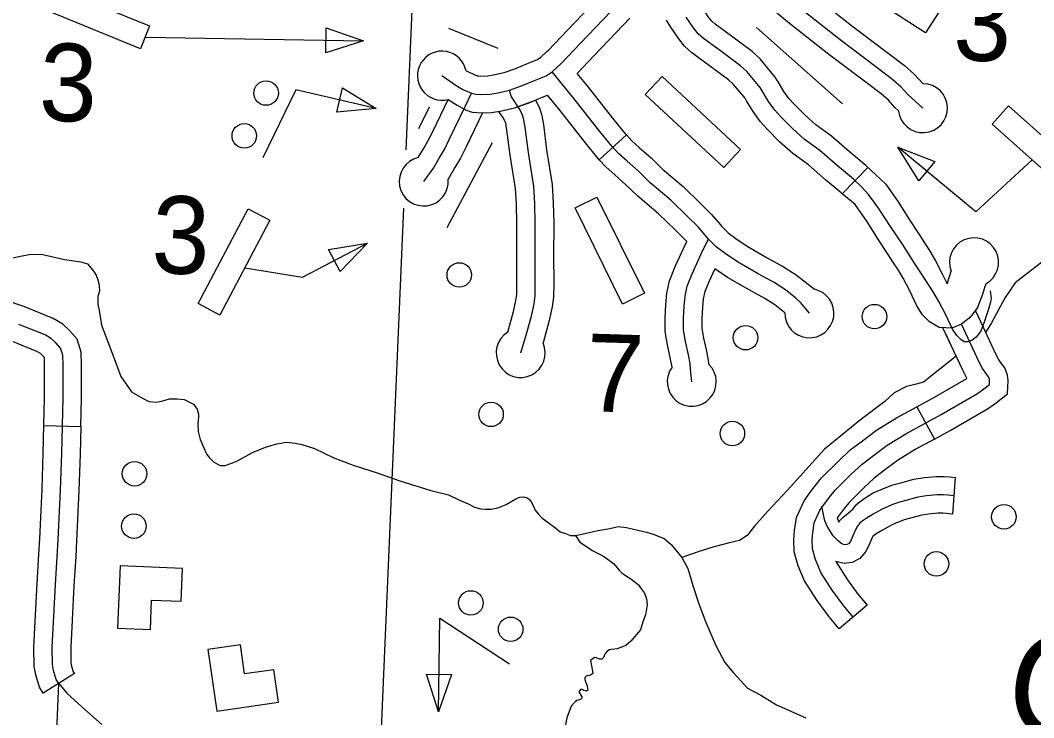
# Model space of a CAD drawing. Extents: x 653372 to 905732, y 627442 to 787275.
# Drawn here: x 662227 to 666359, y 765522 to 768368 of the extents above; entities that cross this region are included whole.
import ezdxf

# ---------------------------------------------------------------- set-up
doc = ezdxf.new("R2010")
doc.units = 0
for name, color, linetype in [('31', 7, 'Continuous'), ('33', 7, 'Continuous'), ('35', 7, 'Continuous'), ('5', 7, 'Continuous'), ('56', 7, 'Continuous'), ('58', 7, 'Continuous'), ('6', 7, 'Continuous')]:
    doc.layers.add(name, color=color, linetype=linetype)

msp = doc.modelspace()

# ---------------------------------------------------------------- linework, layer by layer
at = {"layer": '31'}
for p, q in [((664587.8, 767799), (664698.6, 767900.2)), ((664698.6, 767900.2), (664698.6, 767900.2)), ((665577.6, 767660.4), (665682.3, 767767.7)), ((665883, 766791.2), (665954.7, 766659.4)), ((662323.4, 766714.6), (662473.4, 766711)), ((666039.2, 766503), (666027.4, 766353.5)), ((665680.6, 765981.7), (665565.9, 765884.9)), ((662447.5, 765702.2), (662320.1, 765623.1)), ((662320.1, 765623.1), (662320.1, 765623.1))]:
    msp.add_line(p, q, dxfattribs=at)
for points in [[(665907.2, 768009.4), (665846.2, 768065.8), (665819.1, 768095.2), (665785.3, 768125.6), (665720.6, 768173.9), (665570, 768287.8), (665403.6, 768418.9), (665329.5, 768480.5), (665294.2, 768507.4), (665276.9, 768519.5), (665256.6, 768527), (665232.9, 768532.4), (665195.6, 768536.3), (665156, 768535.4), (665115.6, 768529.1), (664959, 768466.4), (664923.1, 768449), (664901.8, 768433.2)], [(663946.3, 768142.1), (664003.8, 768102.2), (664031.9, 768085.7), (664066.9, 768070.3), (664084.9, 768066.4), (664102.6, 768065.2), (664140.8, 768066.7), (664175.8, 768072.5), (664221, 768082.7), (664270.6, 768100.3), (664323.1, 768122), (664370.7, 768141.7), (664395.5, 768157.4), (664432.9, 768192.3), (664511, 768274.5), (664603.1, 768370.6), (664670.7, 768440.8), (664689.4, 768464.1)], [(664374.1, 768240), (664380.1, 768245.6), (664456.7, 768326.3), (664549.1, 768422.5), (664594.8, 768470.1)], [(665453, 768284.6), (665356.4, 768360.6), (665282.8, 768421.8), (665250, 768446.8), (665241.9, 768452.5), (665235.2, 768454.9), (665220.6, 768458.3), (665192.5, 768461.2), (665162.6, 768460.6), (665135.6, 768456.4), (665069, 768429.6)], [(664497.5, 768151.4), (664565.2, 768222.7), (664657.2, 768318.6), (664712.8, 768376.4)], [(666181.7, 767264.6), (666183.7, 767242), (666185.6, 767234.5), (666182.3, 767218.2), (666173.2, 767185.8), (666157.5, 767135.8), (666143.5, 767100.1), (666132.8, 767085.4), (666124.3, 767074.8), (666107.6, 767062.3), (666092.4, 767056), (666076.1, 767056.5), (666062, 767065.1), (666045.5, 767081.9), (666028.6, 767108.3), (666001, 767165.7), (665972.7, 767221.1), (665948.6, 767260.7), (665907, 767325), (665870.5, 767381.3), (665824.3, 767454.2), (665774.7, 767526.6), (665729.5, 767597.2), (665708.5, 767625.8), (665684.9, 767657.2), (665656.6, 767688.1), (665624.1, 767719.7), (665559, 767774.2), (665487.2, 767836.3), (665423.4, 767882.9), (665375, 767925.9), (665328, 767974.2), (665302.9, 768000.9), (665277.4, 768036.4), (665243.7, 768093.3), (665216.7, 768126.2), (665189.1, 768158.4), (665163.2, 768182.3), (665081.9, 768242.7), (665012.8, 768293.5), (664990.9, 768313.3), (664972.5, 768337), (664942.5, 768380.9)], [(665317.2, 768116.4), (665305.3, 768136.5), (665274.2, 768174.4), (665243.2, 768210.5), (665211.2, 768240.1), (665126.5, 768303), (665060.3, 768351.7), (665046.1, 768364.5), (665033.2, 768381.2), (665014.9, 768407.9)], [(665545.8, 768402.4), (665615.9, 768347.2), (665765.7, 768233.8), (665832.8, 768183.7), (665871.9, 768148.7), (665908, 768109.4)], [(665188.2, 768039.9), (665182.1, 768050.2), (665159.3, 768078), (665135, 768106.3), (665115.2, 768124.6), (665037.3, 768182.4), (664965.4, 768235.3), (664935.7, 768262.1), (664911.9, 768292.8), (664880.1, 768339.3), (664861.4, 768368.1), (664861.4, 768368.1)], [(665807.7, 767999.2), (665793, 768012.8), (665766.4, 768041.8), (665737.7, 768067.5), (665675.6, 768113.9), (665524.2, 768228.4), (665453, 768284.6)], [(664044.3, 768162.1), (664090.2, 768142), (664095.6, 768140.8), (664103.6, 768140.3), (664133.1, 768141.5), (664161.4, 768146.2), (664200.2, 768154.9), (664243.8, 768170.4), (664294.5, 768191.3), (664336, 768208.5), (664349.5, 768217), (664374.1, 768240)], [(665444.5, 767172.6), (665408, 767216.1), (665389.6, 767234.6), (665347.4, 767268.4), (665301.4, 767297.7), (665235.7, 767333.1), (665150.7, 767382.5), (665100.7, 767416), (665063.7, 767444.2), (665032.7, 767475.3), (664990.4, 767524.8), (664949.3, 767566.4), (664879.2, 767634.3), (664794.8, 767705.4), (664747.5, 767751.9), (664701, 767792.9), (664667.6, 767822.8), (664638.8, 767854.3), (664590.2, 767914.4), (664479.9, 768054.8), (664395.5, 768157.4)], [(664698.6, 767900.2), (664695.7, 767903.3), (664648.8, 767961.2), (664538.4, 768101.8), (664497.5, 768151.4)], [(664267.3, 767010.6), (664290.8, 767089), (664310.7, 767161.3), (664321.7, 767211.5), (664326.1, 767244.1), (664326.9, 767293.8), (664326.4, 767413.4), (664326.8, 767539.5), (664325.1, 767620.7), (664321.2, 767690), (664298.8, 767829.1), (664285.5, 767931.7), (664279.1, 767966.7), (664273.5, 767984.6), (664260.6, 768008.1), (664237.8, 768042.9), (664228, 768058.9), (664221, 768082.7)], [(665682.3, 767767.7), (665674.4, 767775.4), (665607.6, 767831.3), (665534, 767895), (665470.5, 767941.3), (665426.8, 767980.2), (665382.2, 768026.1), (665360.9, 768048.7), (665340.3, 768077.5), (665317.2, 768116.4)], [(663849.2, 767807.7), (663870.4, 767844), (663890.5, 767877.2), (663909.9, 767916.9), (663971.3, 768045.3), (664008.5, 768021.3), (664041.8, 768002.4), (664069.4, 767992.6), (664111.3, 767990.5)], [(663872, 767710.3), (663911.2, 767764.9), (663934.9, 767805.7), (663956.4, 767841.2), (663977.4, 767884.2), (664040.7, 768016.6), (664066.9, 768070.3)], [(664111.3, 767990.5), (664148.5, 767992), (664190.1, 767998.9), (664241.9, 768010.6), (664297.5, 768030.3), (664351.7, 768052.6), (664376.2, 768062.8)], [(664251.8, 767531.2), (664251.8, 767538.8), (664250.2, 767617.8), (664246.6, 767681.9), (664224.6, 767818.3), (664211.4, 767920.1), (664206.2, 767948.6), (664204.2, 767955.1), (664196.2, 767969.5), (664178.7, 767996.3), (664241.9, 768010.6), (664327.2, 768042.6)], [(664327.2, 768042.6), (664342.9, 768014.1), (664352, 767984.7), (664359.7, 767943.3), (664373, 767839.8), (664395.9, 767698.1), (664400.1, 767623.6), (664401.8, 767540.1), (664401.8, 767530.8)], [(664587.8, 767799), (664582, 767805.4), (664531.5, 767867.6), (664421.4, 768007.8), (664376.2, 768062.8)], [(665577.6, 767660.4), (665573.8, 767664), (665510.4, 767717), (665440.5, 767777.6), (665376.3, 767824.4), (665323.1, 767871.7), (665273.8, 767922.4), (665244.9, 767953.1), (665214.6, 767995.4), (665188.2, 768039.9)], [(664111.3, 767990.5), (664045, 767851.6), (664022.3, 767805.2), (663999.4, 767767.5), (663971.6, 767719.7)], [(664698.6, 767900.2), (664720.5, 767876.2), (664750.8, 767849), (664798.7, 767806.8), (664845.3, 767760.9), (664929.5, 767690), (665002.1, 767619.7), (665045.7, 767575.6), (665081.4, 767533.8)], [(664944.1, 767465), (664896.5, 767513.1), (664828.9, 767578.6), (664744.3, 767649.9), (664696.4, 767697), (664651.2, 767736.9), (664614.8, 767769.4), (664587.8, 767799)], [(665674.4, 767775.4), (665756.7, 767699.9), (665806.4, 767627.3), (665853.1, 767553.5), (665889.4, 767497.6), (665916.1, 767456.4)], [(665790.3, 767374.7), (665763.5, 767416), (665726.8, 767472.6), (665681.2, 767544.8), (665631.6, 767617), (665577.6, 767660.4)], [(664214.9, 767095.8), (664237.8, 767179.4), (664247.8, 767224.5), (664251.2, 767249.8), (664251.9, 767294.3), (664251.4, 767413.3), (664251.8, 767531.2)], [(664401.8, 767530.8), (664401.4, 767413.4), (664401.9, 767293.3), (664401, 767238.5), (664395.6, 767198.4), (664383.5, 767143.3), (664358.4, 767051.9)], [(665081.4, 767533.8), (665087.8, 767526.2), (665113.2, 767500.8), (665144.4, 767477), (665190.4, 767446.1), (665272.3, 767398.5), (665339.4, 767362.4), (665391, 767329.5), (665464.9, 767270.5)], [(664964.7, 766893.1), (664959.9, 766944.6), (664957.9, 766967.2), (664950.9, 767002.5), (664939, 767057), (664931.4, 767105), (664931, 767151.9), (664933.4, 767201.5), (664937.3, 767242.8), (664945.8, 767283.1), (664966.2, 767333.9), (665010.6, 767430), (665032.7, 767475.3)], [(664931.3, 767437.2), (664944.1, 767465)], [(664884.8, 766953.3), (664865.2, 767043.2), (664856.4, 767098.8), (664856, 767153.4), (664858.6, 767206.8), (664863.1, 767254.1), (664873.7, 767305), (664897.3, 767363.7), (664931.3, 767437.2)], [(665916.1, 767456.4), (665931.7, 767432.4), (665957.7, 767389.5), (665987.7, 767330.9), (666006.2, 767292.4), (666006.2, 767292.6), (666022.4, 767344.1)], [(665058.2, 767354.2), (665035.1, 767304.2), (665017.8, 767261.3), (665011.6, 767231.6), (665008.2, 767196.1), (665006, 767150.4), (665006.3, 767111.2), (665012.7, 767070.9), (665024.3, 767017.9), (665035, 766964.2)], [(665344.6, 767174.6), (665303.7, 767207.3), (665263.4, 767233), (665199.1, 767267.6), (665110.9, 767318.9), (665058.2, 767354.2)], [(666163.5, 767292.7), (666147.8, 767242.6), (666129.3, 767195.6), (666112, 767171.8), (666096.4, 767152.2), (666064.5, 767128.5), (666025.9, 767112.3), (665973.4, 767113.9), (665934.5, 767137.7), (665906, 767166.7), (665882.5, 767203.5), (665853.3, 767264.2), (665826.6, 767316.4), (665804.6, 767352.6), (665790.3, 767374.7)], [(662236.8, 767201.5), (662169.4, 767225.3), (662107.2, 767243.7), (662043.5, 767256.9), (662006, 767261.4), (661970.2, 767264.8), (661918, 767266.3), (661864.4, 767263.4), (661825.6, 767258.5), (661785, 767249.3), (661731.3, 767235.3), (661677.3, 767220.8)], [(662473.4, 766711), (662476.2, 766826.5), (662476.1, 766962.2), (662475.1, 767013.3), (662458.4, 767066.7), (662428.1, 767102.4), (662400.1, 767128.6), (662361.5, 767151.9), (662248.1, 767197.5), (662236.8, 767201.5)], [(666154, 767114.2), (666121.5, 767183.7)], [(662383.8, 765662.7), (662373.8, 765678.8), (662362.7, 765715.7), (662358.3, 765739.2), (662357.4, 765810.3), (662370.6, 766065.1), (662381.8, 766248.7), (662390.9, 766452.6), (662395.7, 766600), (662401.2, 766827.4), (662401.1, 766961.4), (662400.3, 767001.1), (662391.3, 767029.8), (662373.7, 767050.6), (662354.6, 767068.5), (662328, 767084.5), (662221.6, 767127.3)], [(665623.3, 765933.3), (665583.7, 765980.2), (665537.5, 766042.5), (665491.6, 766115.4), (665469.8, 766167.6), (665457, 766211.7), (665455.8, 766246.9), (665457.9, 766278.5), (665463.8, 766318.2), (665487.5, 766369), (665526.6, 766422.4), (665549.7, 766450.4), (665613.7, 766514.1), (665659.6, 766557.2), (665700.3, 766587.6), (665761.1, 766634.1), (665837.5, 766681), (665982, 766759.7), (666129.8, 766845.5), (666155.8, 766863.7), (666178.9, 766881.5), (666179.4, 766895.6), (666178.4, 766903.8), (666175.2, 766913.3), (666167.3, 766922.9), (666150.4, 766946.8), (666137.2, 766973), (666064.5, 767128.5)], [(665883, 766791.2), (665945.2, 766825.1), (666086.7, 766907.1), (666086, 766908.1), (666069.7, 766940.2), (665988.8, 767113.4)], [(665954.7, 766659.4), (666018.7, 766694.3), (666170.2, 766782.2), (666200.2, 766803.2), (666252.8, 766843.8), (666254.5, 766898.6), (666252.1, 766920.3), (666241.8, 766950.4), (666227, 766968.4), (666214.9, 766985.6), (666204.6, 767005.8), (666154, 767114.2)], [(666018.1, 767050.7), (665996.6, 767096.8)], [(662323.4, 766714.6), (662326.2, 766828.3), (662326.1, 766960.6), (662325.5, 766988.8), (662324.3, 766992.9), (662319.2, 766998.9), (662309.1, 767008.3), (662294.4, 767017.2), (662195.1, 767057.1), (662186.8, 767060.1)], [(665449.1, 766443.4), (665467.4, 766468.5), (665494.2, 766500.9), (665561.6, 766568), (665611.3, 766614.8), (665655.1, 766647.5), (665718.6, 766696), (665799.9, 766745.9), (665883, 766791.2)], [(662303.1, 766189.8), (662306.9, 766252.6), (662316, 766455.4), (662320.7, 766602.1), (662323.4, 766714.6)], [(662473.4, 766711), (662470.6, 766597.9), (662465.9, 766449.7), (662456.7, 766244.7), (662452.8, 766180.7)], [(665954.7, 766659.4), (665875.1, 766616.1), (665803.6, 766572.2), (665745.5, 766527.8), (665707.9, 766499.7), (665665.9, 766460.2), (665605.2, 766399.8), (665585.9, 766376.3), (665558.1, 766338.4)], [(665558.1, 766338.4), (665564.2, 766320.2), (665566.1, 766324.6), (665582.8, 766340.9), (665603.7, 766358.1), (665621.2, 766373), (665638, 766394.4), (665667.4, 766417.4), (665704.7, 766439.4), (665737.1, 766453.8), (665760.6, 766463.3), (665784.9, 766472.4), (665817.1, 766481.2), (665870.9, 766496.1), (665913.3, 766502.6), (665961.3, 766506.4), (665994.2, 766506.9), (666015.8, 766504.8), (666039.2, 766503)], [(665565.9, 765884.9), (665524.8, 765933.6), (665475.5, 766000.2), (665424.9, 766080.7), (665398.9, 766142.6), (665382.4, 766199.8), (665380.7, 766248.1), (665383.2, 766286.5), (665391.2, 766340), (665422.7, 766407.4), (665449.1, 766443.4)], [(666033.3, 766428.2), (666009.3, 766430.1), (665991.2, 766431.8), (665964.8, 766431.5), (665921.9, 766428.1), (665886.6, 766422.7), (665837, 766408.9), (665808.1, 766401), (665787.9, 766393.4), (665766.3, 766384.7), (665739, 766372.6), (665705, 766352.5), (665675.8, 766335.8), (665659.1, 766324), (665648.2, 766314.4), (665640.3, 766303.5), (665633.5, 766291.4), (665622.2, 766264.8), (665611.5, 766241.7), (665603.6, 766232.5), (665597.1, 766229.2), (665589.4, 766228.3), (665583, 766229.6), (665573.2, 766234), (665562.4, 766243.7), (665541.9, 766264.3), (665518.4, 766300.7), (665506.8, 766326.3), (665494.8, 766383.9)], [(666027.4, 766353.5), (666002.8, 766355.4), (665988.2, 766356.8), (665968.3, 766356.5), (665930.6, 766353.5), (665902.4, 766349.2), (665856.9, 766336.6), (665831.3, 766329.6), (665815.2, 766323.5), (665795.6, 766315.6), (665773.4, 766305.8), (665742.7, 766287.7), (665716.1, 766272.5), (665705.7, 766265.2), (665704.1, 766263.7), (665703.5, 766262.9), (665700.9, 766258.2), (665690.7, 766234.4), (665675.2, 766200.7), (665650.7, 766172.3), (665619.3, 766156.4), (665586.1, 766152.3), (665552.5, 766159.4)], [(662320.1, 765623.1), (662304.8, 765647.7), (662289.7, 765698), (662283.4, 765731.8), (662282.4, 765811.8), (662295.7, 766069.4), (662303.1, 766189.8)], [(662452.8, 766180.7), (662445.5, 766060.9), (662432.5, 765808.8), (662433.3, 765746.6), (662435.7, 765733.4), (662442.8, 765709.9), (662447.5, 765702.2)], [(665552.5, 766159.4), (665599.5, 766084.9), (665642.5, 766026.8), (665680.6, 765981.7)]]:
    msp.add_lwpolyline(points, dxfattribs=at)
for centre, start, end in [((663946.3, 768142.1), 11.5351, 284.439), ((665907.2, 768009.4), 185.8517, 89.5636), ((663872, 767710.3), 103.1738, 5.375), ((666115.6, 767380.4), 298.6226, 201.3084), ((665444.5, 767172.6), 178.8173, 78.2248), ((664267.3, 767010.6), 121.6288, 24.3966), ((664964.7, 766893.1), 142.986, 45.3521)]:
    msp.add_arc(centre, 100, start, end, dxfattribs=at)
at = {"layer": '33'}
msp.add_lwpolyline([(662383.8, 765662.7), (662416.2, 765622), (662478.5, 765566.4), (662558.9, 765495.3)], dxfattribs=at)
at = {"layer": '35'}
for points in [[(666761.2, 767575.9), (666744.1, 767566.6), (666642.5, 767539.2), (666530.5, 767477), (666434.9, 767414.2), (666283.7, 767296.8), (666242.1, 767237.1), (666187.4, 767133.3), (666163, 767094.8)], [(662170.7, 767393.4), (662227.6, 767406.1), (662270.5, 767413.8), (662318.8, 767412.3), (662407, 767391.7), (662474, 767382.5), (662500.6, 767374.6), (662523.2, 767348.8), (662536.9, 767327.7), (662544.3, 767305.1), (662548.1, 767284.3), (662549.3, 767262.8), (662543.2, 767241.4), (662543.2, 767210), (662550.3, 767177.5), (662557.8, 767123.9), (662606.2, 766998.6)], [(662606.2, 766998.6), (662636.2, 766915.2), (662681, 766852.6), (662724.8, 766825.7), (662751.3, 766813.2), (662781.7, 766810.5), (662808.7, 766815.1), (662835, 766823.2), (662866.4, 766824.1), (662895, 766820.5), (662910.9, 766812.9), (662933, 766801.5), (662948.5, 766781.3), (662953.2, 766760.5), (662952.9, 766750.6), (662950.3, 766722.9), (662952, 766690.6), (662960, 766658), (662975.1, 766623.5), (662987.8, 766596.2), (662998.1, 766582.4), (663014.7, 766566.7), (663033.2, 766555.4), (663043.8, 766551.5), (663062.6, 766551.8), (663107.5, 766568.4), (663174.1, 766605), (663226.7, 766625.8), (663272.8, 766639.7), (663312.5, 766646.6), (663347.4, 766642.8), (663375, 766637.5), (663426.5, 766620.7), (663505.2, 766582.5), (663584.6, 766552.7)], [(666043.2, 766997), (665910.2, 766891.3), (665879.7, 766883.3), (665841, 766873.5), (665790.3, 766848.5), (665752.7, 766813.2), (665652.8, 766737.8), (665506.1, 766618.2), (665355.7, 766450.4), (665273.5, 766363.8), (665220.1, 766304.5), (665190.9, 766265.5), (665159.8, 766245.3), (665112.6, 766235), (665051.2, 766218.1), (664994.4, 766201.1), (664924.6, 766175.5)], [(663584.6, 766552.7), (663682.1, 766521.6), (663774.9, 766488.4), (663900.2, 766449.4), (663973.5, 766432), (664015.1, 766412), (664053.2, 766394.5), (664078.6, 766382), (664104.2, 766375.3), (664120.5, 766373.7), (664147.5, 766372.9), (664174.6, 766379.1), (664207.8, 766392.2), (664247.2, 766415.6), (664263.8, 766422.1), (664280.2, 766424), (664293, 766418.9), (664302.2, 766413.9), (664310.1, 766403.1), (664317.8, 766388.8), (664326.6, 766369.8), (664337.9, 766354.3), (664353.8, 766337.4), (664374.4, 766322.7), (664409.9, 766295.8), (664428.2, 766281.2), (664450.3, 766273.5), (664470, 766265.9), (664491.1, 766266.4), (664516.3, 766271.5), (664582.3, 766286), (664630.6, 766293.9), (664664.8, 766302.2), (664698.7, 766298.9), (664745.3, 766288.1), (664780.1, 766278.9), (664808, 766271), (664852, 766253.3), (664880.6, 766229), (664924.6, 766175.5), (664948.6, 766131), (664969.3, 766061.6), (664994, 765987.1), (665023.2, 765908.8), (665064.9, 765813.8), (665099.2, 765747.2), (665135.5, 765705.1), (665192.2, 765643.6), (665246.4, 765613.8), (665310.8, 765575.6), (665430.4, 765522.2)], [(664491.1, 766266.4), (664508.3, 766239), (664560, 766204.6), (664609.6, 766178.5), (664645.1, 766151.7), (664668.9, 766124), (664679.1, 766113.1), (664694, 766103.3), (664717, 766088.6), (664746.8, 766066.6), (664760.3, 766047.4), (664772.7, 766030.6), (664780.2, 766007), (664783, 765983.4), (664775.9, 765942.6), (664765.6, 765913.6), (664755.3, 765881.1), (664716.8, 765835.1), (664696.3, 765816.4), (664660.4, 765803.1), (664638.1, 765801.4), (664628.7, 765799.4), (664618.9, 765792.9), (664610.6, 765782.3), (664605.5, 765768.4), (664598.2, 765761.6), (664588.8, 765760.7), (664576.7, 765767.4), (664568.5, 765767.6), (664552.4, 765756), (664555.8, 765734.2), (664559.8, 765712.4), (664561.3, 765703), (664549.4, 765694.7), (664538.2, 765693.1), (664534, 765691.5), (664531.6, 765688.6), (664528.5, 765684.6), (664528.9, 765678.1), (664538.1, 765651.5), (664540.2, 765642.7), (664540.5, 765635), (664535.7, 765631.1), (664525.3, 765633.7), (664521.2, 765636.2), (664517.8, 765637.5), (664510.8, 765637.2), (664504.6, 765628), (664516.3, 765608.2), (664516.7, 765602.3), (664512.5, 765598.4), (664506.5, 765595.6), (664495.9, 765593), (664487.5, 765586.2), (664473.7, 765569)], [(664473.7, 765569), (664454.9, 765521.7), (664443.5, 765461.7), (664424.6, 765388.1), (664412.8, 765317.1), (664403.7, 765277.6), (664401.8, 765250.6), (664394.5, 765206.1), (664380.6, 765166.5), (664372.1, 765134.3), (664371.3, 765098), (664366.9, 765066.2), (664360.3, 765053.7)]]:
    msp.add_lwpolyline(points, dxfattribs=at)
at = {"layer": '5'}
for points in [[(663825.1, 768440.3), (663799.3, 767839.2)], [(663789.1, 767600.9), (663685.9, 765193.3)]]:
    msp.add_lwpolyline(points, dxfattribs=at)
at = {"layer": '56'}
for p, q in [((663472.4, 768235.5), (663474.1, 768337.5)), ((663474.1, 768337.5), (663626.2, 768284)), ((663626.2, 768284), (663472.4, 768235.5)), ((663518, 767992.8), (663540.9, 768092.1)), ((663540.9, 768092.1), (663678.6, 768008.1)), ((663678.6, 768008.1), (663518, 767992.8)), ((665890.6, 767713.6), (665805.4, 767850.6)), ((665805.4, 767850.6), (665955.7, 767792.1)), ((665955.7, 767792.1), (665890.6, 767713.6)), ((663483.4, 767433), (663642.6, 767458.4)), ((663530.5, 767342.5), (663483.4, 767433)), ((663642.6, 767458.4), (663530.5, 767342.5)), ((663932.8, 765546.4), (663883.6, 765700)), ((663883.6, 765700), (663985.6, 765698.8)), ((663985.6, 765698.8), (663932.8, 765546.4))]:
    msp.add_line(p, q, dxfattribs=at)
for points in [[(665550.3, 768553.9), (665604.3, 768638), (665972.4, 768401.6), (665918.4, 768317.4)], [(662311.4, 768417.2), (662349.1, 768509.8), (662754.3, 768344.8), (662716.6, 768252.2)], [(664775.4, 768065.8), (664843.5, 768139), (665163.9, 767841.1), (665095.8, 767767.9)], [(666189.2, 767943.9), (666255.6, 768018.7), (666582.7, 767728.1), (666516.2, 767653.3)], [(664488.7, 767602.2), (664578.4, 767646.5), (664772, 767254.2), (664682.4, 767209.9)], [(663156.3, 767598.7), (663244.7, 767551.9), (663040.1, 767165.2), (662951.7, 767212)]]:
    msp.add_lwpolyline(points, close=True, dxfattribs=at)
for points in [[(663973.2, 768336.1), (664173.9, 768254.3)], [(665228.9, 768339.2), (665579.6, 768027.6)], [(662735.5, 768298.5), (663626.2, 768284)], [(663678.6, 768008.1), (663350.2, 768083.7), (663215.8, 767806.3)], [(663893.8, 768013.6), (663851, 767925.4)], [(664150.3, 767868.4), (663966.6, 767521.4)], [(666352.7, 767798.6), (666123.5, 767586.6), (665805.4, 767850.6)], [(663142.4, 767358.5), (663377.1, 767320.1), (663642.6, 767458.4)], [(663932.8, 765546.4), (663937.3, 765929.1), (664221, 765741.6)]]:
    msp.add_lwpolyline(points, dxfattribs=at)
for centre in [(663229.1, 768071.1), (663140.2, 767896.5), (664016.9, 767328.9), (665709.8, 767159), (665184.1, 767072.9), (664146.4, 766760.2), (665130.5, 766682), (662692.8, 766517.8), (666237.5, 766342.1), (662690.2, 766304), (665962.5, 766150.2), (664064, 765990.7), (664226.4, 765883.1)]:
    msp.add_circle(centre, 50, dxfattribs=at)
at = {"layer": '58'}
for points in [[(662634.2, 766141.8), (662623.4, 765888.1), (662757.3, 765882.3), (662762.4, 766002.4), (662882.3, 765997.3), (662888, 766131)], [(663028.3, 765549.2), (663279.7, 765585.7), (663260.4, 765718.3), (663141.5, 765701.1), (663124.2, 765819.8), (662991.8, 765800.6)]]:
    msp.add_lwpolyline(points, close=True, dxfattribs=at)
at = {"layer": '6'}
msp.add_lwpolyline([(659814.6, 768224), (659944.8, 767600), (659979.5, 767248.6), (659995.2, 767175.9), (660182, 766834.1), (660710.6, 766294.9), (661067.8, 766277.7), (661012.9, 764951.1), (662351.5, 764890.2), (662383.8, 765662.7)], dxfattribs=at)

# ---------------------------------------------------------------- texts
at = {"layer": '35'}
msp.add_text('Creek', height=422.4, rotation=350.3389, dxfattribs=at).set_placement((666224.8, 765473.7))
at = {"layer": '56'}
for s, p in [('3', (666028.2, 768205.9)), ('3', (662300.4, 767959.6)), ('3', (662759.4, 767337.1)), ('7', (664529.4, 766773.4))]:
    msp.add_text(s, height=316.8, rotation=358.28, dxfattribs=at).set_placement(p)

doc.saveas('drawing.dxf')
